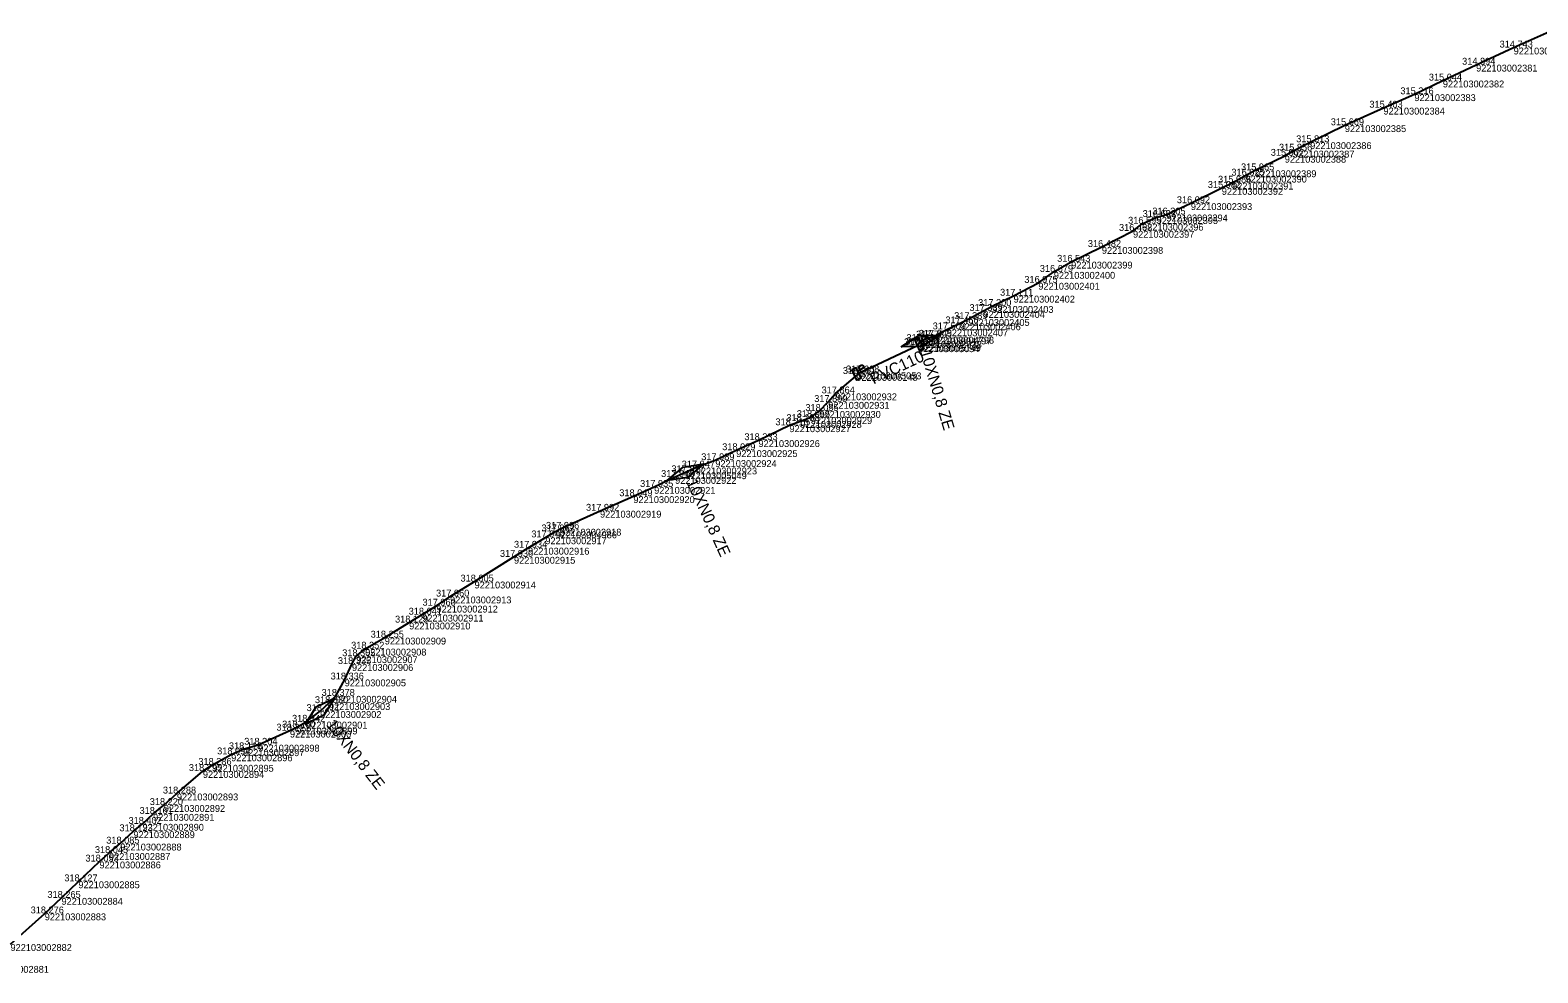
# Model space of a CAD drawing. Extents: x -771047 to -756200, y -1053876 to -1046520.
# Drawn here: x -765508.6 to -765245.3, y -1051497.4 to -1051332.7 of the extents above; entities that cross this region are included whole.
import ezdxf

# ---------------------------------------------------------------- set-up
doc = ezdxf.new("R2010")
doc.units = 0
for name, color, linetype in [('Vrstva 32', 7, 'Continuous'), ('Vrstva 33', 7, 'Continuous'), ('Vrstva 60', 7, 'Continuous'), ('Vrstva 61', 7, 'Continuous')]:
    doc.layers.add(name, color=color, linetype=linetype)

msp = doc.modelspace()

# ---------------------------------------------------------------- linework, layer by layer
at = {"layer": 'Vrstva 32'}
for points in [[(-765511.99, -1051492.34), (-765506.01, -1051486.98), (-765503.08, -1051484.27), (-765500.13, -1051481.38), (-765496.45, -1051477.92), (-765494.79, -1051476.44), (-765492.82, -1051474.79), (-765490.51, -1051472.63), (-765488.93, -1051471.34), (-765487.09, -1051469.6), (-765485.22, -1051468.05), (-765482.93, -1051466.04), (-765478.39, -1051462.11), (-765476.73, -1051461.03), (-765473.45, -1051459.2), (-765471.38, -1051458.31), (-765468.72, -1051457.52), (-765463.19, -1051455.06), (-765462.1, -1051454.52), (-765460.37, -1051453.5), (-765457.92, -1051451.64), (-765456.38, -1051450.25), (-765455.2, -1051448.98), (-765453.63, -1051446.12), (-765452.36, -1051443.43), (-765451.6, -1051442.06), (-765450.06, -1051440.74), (-765446.63, -1051438.81), (-765442.37, -1051436.18), (-765440.09, -1051434.8), (-765437.59, -1051433.23), (-765435.22, -1051431.63), (-765430.94, -1051429.02), (-765424.06, -1051424.7), (-765421.6, -1051423.11), (-765418.58, -1051421.3), (-765416.8, -1051420.25), (-765416.02, -1051419.8), (-765409.03, -1051416.65), (-765403.21, -1051414.11), (-765399.58, -1051412.49), (-765395.92, -1051410.75), (-765394.12, -1051409.93), (-765392.32, -1051409.1), (-765388.9, -1051407.81), (-765385.25, -1051406.07), (-765381.36, -1051404.32), (-765375.95, -1051401.72), (-765374.04, -1051400.98), (-765372.22, -1051400.29), (-765370.72, -1051399.22), (-765369.18, -1051397.65), (-765367.89, -1051396.15), (-765363.62, -1051392.49), (-765353.5, -1051387.75), (-765353.07, -1051387), (-765351.4, -1051386.41), (-765350.93, -1051386.26), (-765348.49, -1051384.97), (-765346.27, -1051383.92), (-765344.72, -1051383.17), (-765342.07, -1051381.76), (-765340.55, -1051380.89), (-765336.81, -1051379.09), (-765332.48, -1051376.84), (-765329.78, -1051374.93), (-765326.75, -1051373.16), (-765321.39, -1051370.58), (-765315.95, -1051367.76), (-765314.36, -1051366.51), (-765311.82, -1051365.35), (-765310.12, -1051364.91), (-765305.85, -1051362.93), (-765300.45, -1051360.27), (-765298.65, -1051359.35), (-765296.31, -1051358.12), (-765294.63, -1051357.19), (-765289.45, -1051354.65), (-765288, -1051353.76), (-765285.01, -1051352.28), (-765278.96, -1051349.31), (-765272.21, -1051346.25), (-765266.81, -1051343.9), (-765261.84, -1051341.51), (-765256.03, -1051338.74), (-765249.48, -1051335.75), (-765242.72, -1051332.71)], [(-765356.42, -1051388.01), (-765353.36, -1051386.05), (-765349.72, -1051386), (-765352.78, -1051387.96), (-765356.42, -1051388.01)], [(-765397.31, -1051411.38), (-765394.54, -1051409.02), (-765390.94, -1051408.48), (-765393.71, -1051410.84), (-765397.31, -1051411.38)], [(-765460.52, -1051453.98), (-765458.59, -1051450.89), (-765455.32, -1051449.3), (-765457.25, -1051452.38), (-765460.52, -1051453.98)]]:
    msp.add_lwpolyline(points, dxfattribs=at)
at = {"layer": 'Vrstva 33'}
for points in [[(-765352.87, -1051386.34), (-765352.4, -1051386.12)], [(-765352.4, -1051386.12), (-765352.23, -1051386.1), (-765352.05, -1051386.23), (-765352, -1051386.33), (-765352.01, -1051386.57), (-765352.14, -1051386.68)], [(-765363.62, -1051392.49), (-765353.5, -1051387.75)], [(-765352.34, -1051387.47), (-765352.87, -1051386.34)], [(-765352.14, -1051386.68), (-765352.61, -1051386.9)], [(-765363.9, -1051391.46), (-765363.42, -1051391.24)], [(-765363.36, -1051392.6), (-765363.9, -1051391.46)], [(-765363.42, -1051391.24), (-765363.26, -1051391.22), (-765363.07, -1051391.36), (-765363.02, -1051391.46), (-765363.04, -1051391.7), (-765363.16, -1051391.8)], [(-765363.16, -1051391.8), (-765363.63, -1051392.02)]]:
    msp.add_lwpolyline(points, dxfattribs=at)
for points in [[(-765354.02, -1051386.88), (-765353.34, -1051386.56), (-765352.49, -1051388.39), (-765353.16, -1051388.7)], [(-765365.04, -1051392), (-765364.37, -1051391.69), (-765363.51, -1051393.51), (-765364.19, -1051393.83)]]:
    msp.add_lwpolyline(points, close=True, dxfattribs=at)
at = {"layer": 'Vrstva 60'}
for p, q in [((-765249.48, -1051335.75), (-765249.48, -1051335.75)), ((-765256.03, -1051338.74), (-765256.03, -1051338.74)), ((-765261.84, -1051341.51), (-765261.84, -1051341.51)), ((-765266.81, -1051343.9), (-765266.81, -1051343.9)), ((-765272.21, -1051346.25), (-765272.21, -1051346.25)), ((-765278.96, -1051349.31), (-765278.96, -1051349.31)), ((-765289.45, -1051354.65), (-765289.45, -1051354.65)), ((-765288, -1051353.76), (-765288, -1051353.76)), ((-765285.01, -1051352.28), (-765285.01, -1051352.28)), ((-765294.63, -1051357.19), (-765294.63, -1051357.19)), ((-765298.65, -1051359.35), (-765298.65, -1051359.35)), ((-765296.31, -1051358.12), (-765296.31, -1051358.12)), ((-765300.45, -1051360.27), (-765300.45, -1051360.27)), ((-765310.12, -1051364.91), (-765310.12, -1051364.91)), ((-765305.85, -1051362.93), (-765305.85, -1051362.93)), ((-765315.95, -1051367.76), (-765315.95, -1051367.76)), ((-765314.36, -1051366.51), (-765314.36, -1051366.51)), ((-765311.82, -1051365.35), (-765311.82, -1051365.35)), ((-765326.75, -1051373.16), (-765326.75, -1051373.16)), ((-765321.39, -1051370.58), (-765321.39, -1051370.58)), ((-765329.78, -1051374.93), (-765329.78, -1051374.93)), ((-765332.48, -1051376.84), (-765332.48, -1051376.84)), ((-765340.55, -1051380.89), (-765340.55, -1051380.89)), ((-765336.81, -1051379.09), (-765336.81, -1051379.09)), ((-765344.72, -1051383.17), (-765344.72, -1051383.17)), ((-765342.07, -1051381.76), (-765342.07, -1051381.76)), ((-765350.93, -1051386.26), (-765350.93, -1051386.26)), ((-765348.49, -1051384.97), (-765348.49, -1051384.97)), ((-765346.27, -1051383.92), (-765346.27, -1051383.92)), ((-765353.5, -1051387.75), (-765353.5, -1051387.75)), ((-765353.25, -1051387.63), (-765353.25, -1051387.63)), ((-765353.07, -1051387), (-765353.07, -1051387)), ((-765351.4, -1051386.41), (-765351.4, -1051386.41)), ((-765364.28, -1051392.76), (-765364.28, -1051392.76)), ((-765363.62, -1051392.49), (-765363.62, -1051392.49)), ((-765367.89, -1051396.15), (-765367.89, -1051396.15)), ((-765370.72, -1051399.22), (-765370.72, -1051399.22)), ((-765369.18, -1051397.65), (-765369.18, -1051397.65)), ((-765375.95, -1051401.72), (-765375.95, -1051401.72)), ((-765374.04, -1051400.98), (-765374.04, -1051400.98)), ((-765372.22, -1051400.29), (-765372.22, -1051400.29)), ((-765381.36, -1051404.32), (-765381.36, -1051404.32)), ((-765385.25, -1051406.07), (-765385.25, -1051406.07)), ((-765394.12, -1051409.93), (-765394.12, -1051409.93)), ((-765392.32, -1051409.1), (-765392.32, -1051409.1)), ((-765388.9, -1051407.81), (-765388.9, -1051407.81)), ((-765399.58, -1051412.49), (-765399.58, -1051412.49)), ((-765395.92, -1051410.75), (-765395.92, -1051410.75)), ((-765403.21, -1051414.11), (-765403.21, -1051414.11)), ((-765409.03, -1051416.65), (-765409.03, -1051416.65)), ((-765416.8, -1051420.25), (-765416.8, -1051420.25)), ((-765416.02, -1051419.8), (-765416.02, -1051419.8)), ((-765421.6, -1051423.11), (-765421.6, -1051423.11)), ((-765418.58, -1051421.3), (-765418.58, -1051421.3)), ((-765424.06, -1051424.7), (-765424.06, -1051424.7)), ((-765430.94, -1051429.02), (-765430.94, -1051429.02)), ((-765437.59, -1051433.23), (-765437.59, -1051433.23)), ((-765435.22, -1051431.63), (-765435.22, -1051431.63)), ((-765442.37, -1051436.18), (-765442.37, -1051436.18)), ((-765440.09, -1051434.8), (-765440.09, -1051434.8)), ((-765446.63, -1051438.81), (-765446.63, -1051438.81)), ((-765450.06, -1051440.74), (-765450.06, -1051440.74)), ((-765452.36, -1051443.43), (-765452.36, -1051443.43)), ((-765451.6, -1051442.06), (-765451.6, -1051442.06)), ((-765453.63, -1051446.12), (-765453.63, -1051446.12)), ((-765455.2, -1051448.98), (-765455.2, -1051448.98)), ((-765457.92, -1051451.64), (-765457.92, -1051451.64)), ((-765456.38, -1051450.25), (-765456.38, -1051450.25)), ((-765462.1, -1051454.52), (-765462.1, -1051454.52)), ((-765460.37, -1051453.5), (-765460.37, -1051453.5)), ((-765463.19, -1051455.06), (-765463.19, -1051455.06)), ((-765473.45, -1051459.2), (-765473.45, -1051459.2)), ((-765471.38, -1051458.31), (-765471.38, -1051458.31)), ((-765468.72, -1051457.52), (-765468.72, -1051457.52)), ((-765478.39, -1051462.11), (-765478.39, -1051462.11)), ((-765476.73, -1051461.03), (-765476.73, -1051461.03)), ((-765482.93, -1051466.04), (-765482.93, -1051466.04)), ((-765487.09, -1051469.6), (-765487.09, -1051469.6)), ((-765485.22, -1051468.05), (-765485.22, -1051468.05)), ((-765490.51, -1051472.63), (-765490.51, -1051472.63)), ((-765488.93, -1051471.34), (-765488.93, -1051471.34)), ((-765492.82, -1051474.79), (-765492.82, -1051474.79)), ((-765496.45, -1051477.92), (-765496.45, -1051477.92)), ((-765494.79, -1051476.44), (-765494.79, -1051476.44)), ((-765500.13, -1051481.38), (-765500.13, -1051481.38)), ((-765503.08, -1051484.27), (-765503.08, -1051484.27)), ((-765506.01, -1051486.98), (-765506.01, -1051486.98))]:
    msp.add_line(p, q, dxfattribs=at)

# ---------------------------------------------------------------- texts
at = {"layer": 'Vrstva 32'}
for rotation, p in [(286.6635, (-765353.16, -1051388.81)), (294.4992, (-765394.01, -1051411.62)), (307.7433, (-765456.95, -1051454.03))]:
    msp.add_text('10XN0,8 ZE', height=2, rotation=rotation, dxfattribs=at).set_placement(p)
at = {"layer": 'Vrstva 33'}
msp.add_text('PVC110', height=2, rotation=25.09, dxfattribs=at).set_placement((-765361.27, -1051394.61))
at = {"layer": 'Vrstva 60'}
for s, p in [('922103002380', (-765249.48, -1051336.95)), ('922103002381', (-765256.03, -1051339.94)), ('922103002382', (-765261.84, -1051342.71)), ('922103002383', (-765266.81, -1051345.1)), ('922103002384', (-765272.21, -1051347.45)), ('922103002385', (-765278.96, -1051350.51)), ('922103002388', (-765289.45, -1051355.85)), ('922103002387', (-765288, -1051354.96)), ('922103002386', (-765285.01, -1051353.48)), ('922103002389', (-765294.63, -1051358.39)), ('922103002391', (-765298.65, -1051360.55)), ('922103002390', (-765296.31, -1051359.32)), ('922103002392', (-765300.45, -1051361.47)), ('922103002394', (-765310.12, -1051366.11)), ('922103002393', (-765305.85, -1051364.13)), ('922103002397', (-765315.95, -1051368.96)), ('922103002396', (-765314.36, -1051367.71)), ('922103002395', (-765311.82, -1051366.55)), ('922103002399', (-765326.75, -1051374.35)), ('922103002398', (-765321.39, -1051371.78)), ('922103002400', (-765329.78, -1051376.13)), ('922103002401', (-765332.48, -1051378.04)), ('922103002403', (-765340.55, -1051382.09)), ('922103002402', (-765336.81, -1051380.29)), ('922103002405', (-765344.72, -1051384.37)), ('922103002404', (-765342.07, -1051382.96)), ('922103004798', (-765350.93, -1051387.46)), ('922103002407', (-765348.49, -1051386.17)), ('922103002406', (-765346.27, -1051385.12)), ('922103005054', (-765353.5, -1051388.95)), ('922103005149', (-765353.25, -1051388.83)), ('922103002933', (-765353.07, -1051388.2)), ('922103004797', (-765351.4, -1051387.6)), ('922103005148', (-765364.28, -1051393.96)), ('922103005053', (-765363.62, -1051393.69)), ('922103002932', (-765367.89, -1051397.35)), ('922103002930', (-765370.72, -1051400.42)), ('922103002931', (-765369.18, -1051398.84)), ('922103002927', (-765375.95, -1051402.92)), ('922103002928', (-765374.04, -1051402.18)), ('922103002929', (-765372.22, -1051401.49)), ('922103002926', (-765381.36, -1051405.52)), ('922103002925', (-765385.25, -1051407.27)), ('922103005049', (-765394.12, -1051411.13)), ('922103002923', (-765392.32, -1051410.3)), ('922103002924', (-765388.9, -1051409.01)), ('922103002921', (-765399.58, -1051413.69)), ('922103002922', (-765395.92, -1051411.95)), ('922103002920', (-765403.21, -1051415.31)), ('922103002919', (-765409.03, -1051417.85)), ('922103004986', (-765416.8, -1051421.45)), ('922103002918', (-765416.02, -1051421)), ('922103002916', (-765421.6, -1051424.31)), ('922103002917', (-765418.58, -1051422.5)), ('922103002915', (-765424.06, -1051425.9)), ('922103002914', (-765430.94, -1051430.22)), ('922103002912', (-765437.59, -1051434.43)), ('922103002913', (-765435.22, -1051432.83)), ('922103002910', (-765442.37, -1051437.38)), ('922103002911', (-765440.09, -1051436)), ('922103002909', (-765446.63, -1051440.01)), ('922103002908', (-765450.06, -1051441.94)), ('922103002906', (-765452.36, -1051444.63)), ('922103002907', (-765451.6, -1051443.26)), ('922103002905', (-765453.63, -1051447.32)), ('922103002904', (-765455.2, -1051450.18)), ('922103002902', (-765457.92, -1051452.84)), ('922103002903', (-765456.38, -1051451.45)), ('922103002899', (-765462.1, -1051455.72)), ('922103002901', (-765460.37, -1051454.7)), ('922103002900', (-765463.19, -1051456.26)), ('922103002896', (-765473.45, -1051460.4)), ('922103002897', (-765471.38, -1051459.51)), ('922103002898', (-765468.72, -1051458.72)), ('922103002894', (-765478.39, -1051463.31)), ('922103002895', (-765476.73, -1051462.23)), ('922103002893', (-765482.93, -1051467.24)), ('922103002891', (-765487.09, -1051470.8)), ('922103002892', (-765485.22, -1051469.25)), ('922103002889', (-765490.51, -1051473.83)), ('922103002890', (-765488.93, -1051472.54)), ('922103002888', (-765492.82, -1051475.99)), ('922103002886', (-765496.45, -1051479.12)), ('922103002887', (-765494.79, -1051477.64)), ('922103002885', (-765500.13, -1051482.58)), ('922103002884', (-765503.08, -1051485.47)), ('922103002883', (-765506.01, -1051488.18)), ('922103002882', (-765511.99, -1051493.54)), ('922103002881', (-765515.99, -1051497.35))]:
    msp.add_text(s, height=1.2, dxfattribs=at).set_placement(p)
at = {"layer": 'Vrstva 61'}
for s, p in [('314.743', (-765251.93, -1051335.75)), ('314.894', (-765258.48, -1051338.74)), ('315.044', (-765264.29, -1051341.51)), ('315.216', (-765269.26, -1051343.9)), ('315.403', (-765274.67, -1051346.25)), ('315.669', (-765281.41, -1051349.31)), ('315.813', (-765287.46, -1051352.28)), ('315.902', (-765291.9, -1051354.65)), ('315.856', (-765290.46, -1051353.76)), ('316.025', (-765298.77, -1051358.12)), ('315.965', (-765297.09, -1051357.19)), ('315.982', (-765302.89, -1051360.27)), ('315.986', (-765301.1, -1051359.35)), ('316.092', (-765308.3, -1051362.93)), ('316.633', (-765314.27, -1051365.35)), ('316.305', (-765312.58, -1051364.91)), ('316.468', (-765318.4, -1051367.76)), ('316.595', (-765316.81, -1051366.51)), ('316.482', (-765323.84, -1051370.58)), ('316.543', (-765329.2, -1051373.16)), ('316.975', (-765334.93, -1051376.84)), ('316.679', (-765332.23, -1051374.93)), ('317.111', (-765339.17, -1051379.09)), ('317.339', (-765344.52, -1051381.76)), ('317.200', (-765343, -1051380.89)), ('317.450', (-765348.72, -1051383.92)), ('317.389', (-765347.18, -1051383.17)), ('317.634', (-765355.52, -1051387)), ('317.737', (-765353.85, -1051386.41)), ('317.845', (-765353.38, -1051386.26)), ('317.509', (-765350.94, -1051384.97)), ('317.617', (-765355.95, -1051387.75)), ('318.380', (-765355.7, -1051387.63)), ('318.391', (-765366.63, -1051392.76)), ('317.668', (-765366.07, -1051392.49)), ('317.899', (-765371.63, -1051397.65)), ('317.864', (-765370.34, -1051396.15)), ('318.056', (-765374.67, -1051400.29)), ('318.055', (-765373.17, -1051399.22)), ('318.216', (-765378.4, -1051401.72)), ('318.188', (-765376.49, -1051400.98)), ('318.233', (-765383.82, -1051404.32)), ('317.989', (-765391.36, -1051407.81)), ('318.029', (-765387.7, -1051406.07)), ('317.945', (-765398.37, -1051410.75)), ('317.817', (-765396.57, -1051409.93)), ('317.947', (-765394.77, -1051409.1)), ('317.935', (-765402.04, -1051412.49)), ('318.049', (-765405.67, -1051414.11)), ('317.992', (-765411.48, -1051416.65)), ('317.940', (-765421.03, -1051421.3)), ('317.962', (-765419.25, -1051420.25)), ('317.996', (-765418.47, -1051419.8)), ('317.934', (-765424.06, -1051423.11)), ('317.930', (-765426.51, -1051424.7)), ('318.005', (-765433.4, -1051429.02)), ('317.960', (-765437.67, -1051431.63)), ('318.041', (-765442.45, -1051434.8)), ('317.960', (-765440.04, -1051433.23)), ('318.129', (-765444.83, -1051436.18)), ('318.255', (-765449.09, -1051438.81)), ('318.305', (-765454.06, -1051442.06)), ('318.352', (-765452.5, -1051440.74)), ('318.335', (-765454.81, -1051443.43)), ('318.336', (-765456.08, -1051446.12)), ('318.330', (-765458.83, -1051450.25)), ('318.378', (-765457.66, -1051448.98)), ('318.211', (-765460.28, -1051451.64)), ('318.221', (-765465.55, -1051455.06)), ('318.260', (-765464.55, -1051454.52)), ('318.342', (-765462.82, -1051453.5)), ('318.118', (-765473.84, -1051458.31)), ('318.204', (-765471.17, -1051457.52)), ('318.286', (-765479.18, -1051461.03)), ('318.094', (-765475.9, -1051459.2)), ('318.295', (-765480.84, -1051462.11)), ('318.288', (-765485.38, -1051466.04)), ('318.220', (-765487.67, -1051468.05)), ('318.402', (-765491.38, -1051471.34)), ('318.161', (-765489.45, -1051469.6)), ('318.123', (-765492.96, -1051472.63)), ('318.045', (-765497.25, -1051476.44)), ('318.085', (-765495.27, -1051474.79)), ('318.053', (-765498.9, -1051477.92)), ('318.127', (-765502.59, -1051481.38)), ('318.265', (-765505.54, -1051484.27)), ('318.276', (-765508.47, -1051486.98))]:
    msp.add_text(s, height=1.2, dxfattribs=at).set_placement(p)

doc.saveas('drawing.dxf')
